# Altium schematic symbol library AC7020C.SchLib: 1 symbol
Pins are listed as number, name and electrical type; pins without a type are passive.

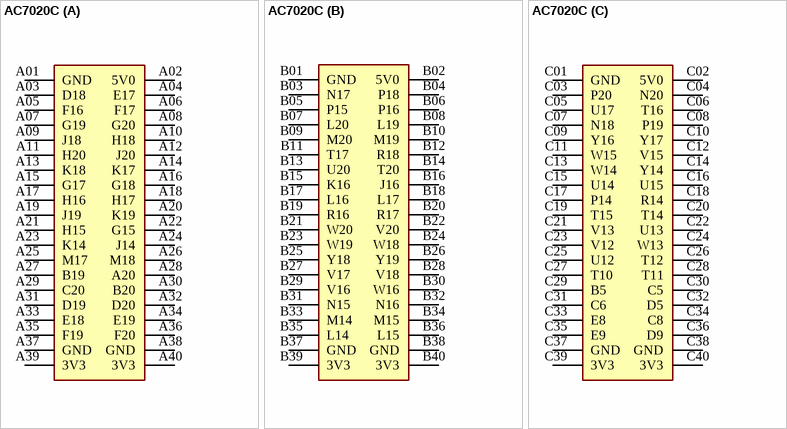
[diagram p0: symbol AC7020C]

## AC7020C
designator U?, comment LGA506  (value not drawn)
footprint AC7020C
part A pins: A01 GND, A02 5V0, A03 D18, A04 E17, A05 F16, A06 F17, A07 G19, A08 G20, A09 J18, A10 H18, A11 H20, A12 J20, A13 K18, A14 K17, A15 G17, A16 G18, A17 H16, A18 H17, A19 J19, A20 K19, A21 H15, A22 G15, A23 K14, A24 J14, A25 M17, A26 M18, A27 B19, A28 A20, A29 C20, A30 B20, A31 D19, A32 D20, A33 E18, A34 E19, A35 F19, A36 F20, A37 GND, A38 GND, A39 3V3, A40 3V3
part B pins: B01 GND, B02 5V0, B03 N17, B04 P18, B05 P15, B06 P16, B07 L20, B08 L19, B09 M20, B10 M19, B11 T17, B12 R18, B13 U20, B14 T20, B15 K16, B16 J16, B17 L16, B18 L17, B19 R16, B20 R17, B21 W20, B22 V20, B23 W19, B24 W18, B25 Y18, B26 Y19, B27 V17, B28 V18, B29 V16, B30 W16, B31 N15, B32 N16, B33 M14, B34 M15, B35 L14, B36 L15, B37 GND, B38 GND, B39 3V3, B40 3V3
part C pins: C01 GND, C02 5V0, C03 P20, C04 N20, C05 U17, C06 T16, C07 N18, C08 P19, C09 Y16, C10 Y17, C11 W15, C12 V15, C13 W14, C14 Y14, C15 U14, C16 U15, C17 P14, C18 R14, C19 T15, C20 T14, C21 V13, C22 U13, C23 V12, C24 W13, C25 U12, C26 T12, C27 T10, C28 T11, C29 B5, C30 C5, C31 C6, C32 D5, C33 E8, C34 C8, C35 E9, C36 D9, C37 GND, C38 GND, C39 3V3, C40 3V3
